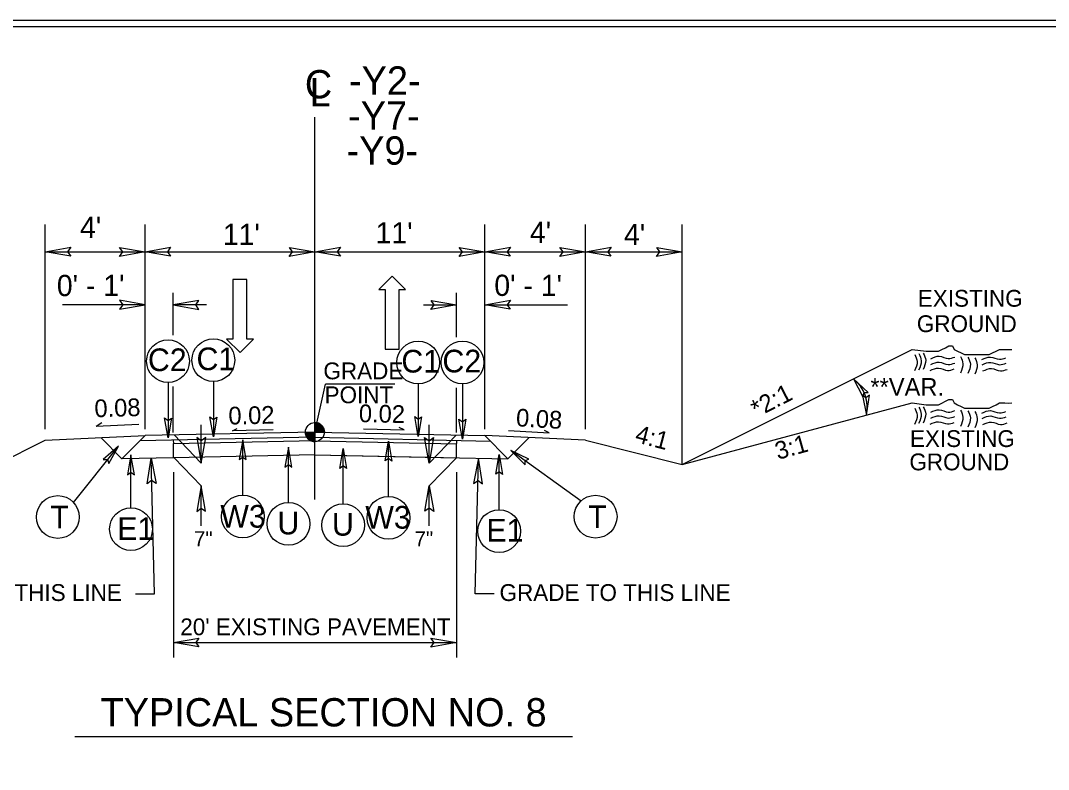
# Model space of a CAD drawing. Extents: x 573813 to 575363, y -54752 to -53123.
# Drawn here: x 574831.2 to 574913.7, y -53847.8 to -53787.7 of the extents above; entities that cross this region are included whole.
import ezdxf

# ---------------------------------------------------------------- set-up
doc = ezdxf.new("R2010")
doc.units = 0
for name, color, linetype in [('Old_Level_1', 7, 'Continuous'), ('Old_Level_11', 7, 'Continuous'), ('Old_Level_2', 7, 'Continuous'), ('Old_Level_3', 7, 'Continuous'), ('Prop Lane Arrow CELL', 7, 'Continuous'), ('Prop Pavement Schedule Description CELL', 7, 'Continuous'), ('Sheet Plot Border Inside CELL', 7, 'Continuous'), ('Sheet Typical CELL', 7, 'Continuous'), ('Typical Grade Point Symbol CELL', 7, 'Continuous'), ('Typical ID Circle CELL', 7, 'Continuous'), ('Typical Terminator CELL', 7, 'Continuous'), ('Typical Text ID Circle CELL', 7, 'Continuous')]:
    doc.layers.add(name, color=color, linetype=linetype)

msp = doc.modelspace()

# ---------------------------------------------------------------- linework, layer by layer
at = {"layer": 'Old_Level_1'}
for p, q in [((574884.321, -53823.332), (574902.797, -53814.094)), ((574884.321, -53823.332), (574902.797, -53818.396)), ((574854.816, -53820.732), (574841.173, -53821.015)), ((574848.192, -53820.63), (574848.571, -53820.44)), ((574851.461, -53820.562), (574848.192, -53820.63)), ((574854.816, -53820.732), (574868.46, -53821.015)), ((574858.709, -53820.477), (574861.972, -53820.545)), ((574861.972, -53820.545), (574861.593, -53820.356)), ((574799.389, -53838.269), (574833.158, -53821.384)), ((574833.158, -53821.384), (574841.173, -53821.015)), ((574837.62, -53821.179), (574839.315, -53822.874)), ((574841.173, -53821.015), (574839.315, -53822.874)), ((574854.816, -53821.14), (574840.755, -53821.433)), ((574843.444, -53821.377), (574843.447, -53821.662)), ((574854.816, -53821.435), (574843.447, -53821.663)), ((574843.447, -53822.788), (574843.447, -53821.662)), ((574854.816, -53821.14), (574868.915, -53821.471)), ((574854.816, -53821.435), (574866.186, -53821.663)), ((574866.189, -53821.407), (574866.186, -53821.661)), ((574866.186, -53822.788), (574866.186, -53821.661)), ((574868.46, -53821.015), (574870.318, -53822.874)), ((574876.54, -53821.387), (574868.46, -53821.015)), ((574872.013, -53821.179), (574870.318, -53822.874)), ((574876.54, -53821.387), (574884.321, -53823.332)), ((574854.816, -53822.552), (574843.447, -53822.788)), ((574854.816, -53822.551), (574866.186, -53822.788)), ((574854.816, -53822.551), (574870.318, -53822.874)), ((574843.447, -53822.788), (574839.315, -53822.874))]:
    msp.add_line(p, q, dxfattribs=at)
for points in [[(574902.797, -53814.094), (574903.917, -53814.234), (574904.198, -53814.234), (574904.618, -53814.234), (574904.898, -53814.234), (574905.179, -53814.094), (574905.459, -53813.954), (574905.739, -53813.813), (574906.019, -53813.813), (574906.16, -53814.094), (574906.44, -53814.234), (574906.72, -53814.374), (574907, -53814.514), (574907.28, -53814.514), (574907.561, -53814.514), (574907.841, -53814.514), (574908.121, -53814.514), (574908.401, -53814.514), (574908.681, -53814.514), (574908.961, -53814.514), (574909.242, -53814.374), (574909.522, -53814.234), (574909.802, -53814.094), (574910.223, -53814.094), (574910.503, -53814.094), (574910.783, -53814.094)], [(574902.797, -53818.396), (574903.917, -53818.536), (574904.198, -53818.536), (574904.618, -53818.536), (574904.898, -53818.536), (574905.179, -53818.397), (574905.459, -53818.256), (574905.739, -53818.115), (574906.019, -53818.115), (574906.16, -53818.396), (574906.44, -53818.536), (574906.72, -53818.677), (574907, -53818.816), (574907.28, -53818.816), (574907.561, -53818.816), (574907.841, -53818.816), (574908.121, -53818.816), (574908.401, -53818.816), (574908.681, -53818.816), (574908.961, -53818.816), (574909.242, -53818.677), (574909.522, -53818.536), (574909.802, -53818.396), (574910.223, -53818.396), (574910.503, -53818.397), (574910.783, -53818.396)]]:
    msp.add_lwpolyline(points, dxfattribs=at)
at = {"layer": 'Old_Level_11'}
for p, q in [((574833.158, -53820.494), (574833.158, -53804.056)), ((574841.173, -53820.494), (574841.173, -53804.056)), ((574868.46, -53820.494), (574868.46, -53804.056)), ((574876.54, -53820.494), (574876.54, -53804.056)), ((574884.321, -53823.295), (574884.321, -53804.056)), ((574833.158, -53806.256), (574841.173, -53806.256)), ((574841.173, -53806.256), (574854.816, -53806.256)), ((574854.816, -53806.256), (574868.46, -53806.256)), ((574868.46, -53806.256), (574876.54, -53806.256)), ((574876.54, -53806.256), (574884.321, -53806.256)), ((574843.444, -53812.959), (574843.444, -53809.559)), ((574866.189, -53813.118), (574866.189, -53809.559)), ((574841.173, -53810.514), (574834.531, -53810.514)), ((574846.104, -53810.514), (574843.444, -53810.514)), ((574863.529, -53810.514), (574866.189, -53810.514)), ((574868.46, -53810.514), (574875.102, -53810.514)), ((574843.444, -53820.768), (574843.444, -53817.071)), ((574854.816, -53820.732), (574855.66, -53816.884)), ((574861.226, -53816.884), (574855.66, -53816.884)), ((574866.189, -53820.768), (574866.189, -53817.188)), ((574845.691, -53823.22), (574845.691, -53820.144)), ((574863.994, -53823.221), (574863.994, -53820.145)), ((574843.506, -53820.957), (574845.691, -53823.22)), ((574866.169, -53820.968), (574863.994, -53823.221)), ((574841.933, -53833.725), (574841.666, -53822.825)), ((574843.499, -53822.787), (574845.684, -53825.049)), ((574866.186, -53822.788), (574864.001, -53825.051)), ((574867.7, -53833.725), (574867.967, -53822.825)), ((574843.447, -53823.959), (574843.447, -53838.833)), ((574866.186, -53823.959), (574866.186, -53838.833)), ((574845.684, -53828.261), (574845.684, -53825.049)), ((574864.001, -53828.262), (574864.001, -53825.051)), ((574840.42, -53833.725), (574841.933, -53833.725)), ((574869.213, -53833.725), (574867.7, -53833.725)), ((574843.447, -53837.641), (574866.186, -53837.641)), ((574835.537, -53845.192), (574875.496, -53845.192))]:
    msp.add_line(p, q, dxfattribs=at)
for points in [[(574835.204, -53806.608), (574833.158, -53806.256), (574835.216, -53805.892), (574834.954, -53806.256)], [(574839.126, -53805.904), (574841.173, -53806.256), (574839.115, -53806.62), (574839.376, -53806.256)], [(574843.219, -53806.608), (574841.173, -53806.256), (574843.231, -53805.892), (574842.969, -53806.256)], [(574852.77, -53805.904), (574854.816, -53806.256), (574852.759, -53806.62), (574853.02, -53806.256)], [(574856.863, -53806.608), (574854.816, -53806.256), (574856.874, -53805.892), (574856.613, -53806.256)], [(574866.414, -53805.904), (574868.46, -53806.256), (574866.402, -53806.62), (574866.664, -53806.256)], [(574870.507, -53806.608), (574868.46, -53806.256), (574870.518, -53805.892), (574870.257, -53806.256)], [(574874.494, -53805.904), (574876.54, -53806.256), (574874.482, -53806.62), (574874.744, -53806.256)], [(574878.587, -53806.609), (574876.54, -53806.256), (574878.598, -53805.892), (574878.337, -53806.256)], [(574882.275, -53805.904), (574884.321, -53806.256), (574882.263, -53806.62), (574882.524, -53806.256)], [(574839.126, -53810.866), (574841.173, -53810.514), (574839.115, -53810.15), (574839.376, -53810.514)], [(574845.491, -53810.161), (574843.444, -53810.514), (574845.502, -53810.877), (574845.241, -53810.514)], [(574864.142, -53810.161), (574866.189, -53810.514), (574864.131, -53810.877), (574864.392, -53810.514)], [(574870.507, -53810.866), (574868.46, -53810.514), (574870.518, -53810.15), (574870.257, -53810.514)], [(574845.339, -53821.173), (574845.691, -53823.22), (574846.055, -53821.162), (574845.691, -53821.423)], [(574864.346, -53821.174), (574863.994, -53823.221), (574863.63, -53821.163), (574863.994, -53821.424)], [(574841.357, -53824.878), (574841.666, -53822.825), (574842.074, -53824.874), (574841.704, -53824.621)], [(574868.276, -53824.878), (574867.967, -53822.825), (574867.559, -53824.874), (574867.928, -53824.621)], [(574846.036, -53827.096), (574845.684, -53825.049), (574845.32, -53827.107), (574845.683, -53826.846)], [(574863.649, -53827.097), (574864.001, -53825.051), (574864.365, -53827.109), (574864.002, -53826.847)], [(574845.493, -53837.993), (574843.447, -53837.641), (574845.505, -53837.277), (574845.243, -53837.641)], [(574864.14, -53837.288), (574866.186, -53837.641), (574864.128, -53838.005), (574864.39, -53837.641)]]:
    msp.add_lwpolyline(points, close=True, dxfattribs=at)
msp.add_arc((574896.259, -53818.758), 2.919, 347.68026, 51.87229, dxfattribs=at)
at = {"layer": 'Old_Level_2'}
for p, q in [((574854.816, -53826.151), (574854.816, -53795.432)), ((574837.257, -53820.252), (574837.711, -53819.959)), ((574837.257, -53820.252), (574840.687, -53820.085)), ((574870.378, -53820.593), (574873.628, -53820.787)), ((574873.628, -53820.787), (574873.245, -53820.605))]:
    msp.add_line(p, q, dxfattribs=at)
for points in [[(574902.992, -53814.497), (574903.184, -53815.061), (574902.977, -53815.81)], [(574902.992, -53814.497), (574903.184, -53815.061), (574902.977, -53815.81)], [(574903.324, -53814.432), (574903.514, -53814.998), (574903.307, -53815.748)], [(574903.324, -53814.432), (574903.514, -53814.998), (574903.307, -53815.748)], [(574903.678, -53814.395), (574903.872, -53814.961), (574903.664, -53815.708)], [(574903.678, -53814.395), (574903.872, -53814.961), (574903.664, -53815.708)], [(574904.278, -53815.311), (574904.964, -53815.118), (574905.684, -53815.302), (574906.204, -53815.185)], [(574904.278, -53815.311), (574904.964, -53815.118), (574905.684, -53815.302), (574906.204, -53815.185)], [(574904.282, -53814.836), (574904.964, -53814.639), (574905.69, -53814.823), (574906.209, -53814.706)], [(574906.674, -53814.674), (574906.864, -53815.238), (574906.66, -53815.987)], [(574906.674, -53814.674), (574906.864, -53815.238), (574906.66, -53815.987)], [(574907.27, -53814.72), (574907.462, -53815.286), (574907.257, -53816.035)], [(574907.27, -53814.72), (574907.462, -53815.286), (574907.257, -53816.035)], [(574907.822, -53814.77), (574908.014, -53815.336), (574907.806, -53816.083)], [(574907.822, -53814.77), (574908.014, -53815.336), (574907.806, -53816.083)], [(574908.387, -53814.9), (574909.073, -53814.705), (574909.793, -53814.889), (574910.316, -53814.774)], [(574908.406, -53815.329), (574909.091, -53815.132), (574909.811, -53815.319), (574910.334, -53815.201)], [(574908.406, -53815.329), (574909.091, -53815.132), (574909.811, -53815.319), (574910.334, -53815.201)], [(574904.225, -53815.792), (574904.909, -53815.599), (574905.635, -53815.779), (574906.156, -53815.664)], [(574904.225, -53815.792), (574904.909, -53815.599), (574905.635, -53815.779), (574906.156, -53815.664)], [(574908.475, -53815.826), (574909.159, -53815.63), (574909.883, -53815.815), (574910.403, -53815.697)], [(574908.475, -53815.826), (574909.159, -53815.63), (574909.883, -53815.815), (574910.403, -53815.697)], [(574902.992, -53818.799), (574903.184, -53819.363), (574902.977, -53820.112)], [(574902.992, -53818.799), (574903.184, -53819.363), (574902.977, -53820.112)], [(574903.324, -53818.734), (574903.514, -53819.3), (574903.307, -53820.05)], [(574903.324, -53818.734), (574903.514, -53819.3), (574903.307, -53820.05)], [(574903.678, -53818.697), (574903.872, -53819.263), (574903.664, -53820.01)], [(574903.678, -53818.697), (574903.872, -53819.263), (574903.664, -53820.01)], [(574904.282, -53819.138), (574904.964, -53818.941), (574905.69, -53819.125), (574906.209, -53819.008)], [(574906.674, -53818.976), (574906.864, -53819.54), (574906.66, -53820.29)], [(574906.674, -53818.976), (574906.864, -53819.54), (574906.66, -53820.29)], [(574907.27, -53819.022), (574907.462, -53819.588), (574907.257, -53820.338)], [(574907.27, -53819.022), (574907.462, -53819.588), (574907.257, -53820.338)], [(574907.822, -53819.072), (574908.014, -53819.638), (574907.806, -53820.385)], [(574907.822, -53819.072), (574908.014, -53819.638), (574907.806, -53820.385)], [(574908.387, -53819.202), (574909.073, -53819.007), (574909.793, -53819.192), (574910.316, -53819.076)], [(574904.225, -53820.094), (574904.909, -53819.901), (574905.635, -53820.081), (574906.156, -53819.966)], [(574904.225, -53820.094), (574904.909, -53819.901), (574905.635, -53820.081), (574906.156, -53819.966)], [(574904.278, -53819.613), (574904.964, -53819.42), (574905.684, -53819.605), (574906.204, -53819.487)], [(574904.278, -53819.613), (574904.964, -53819.42), (574905.684, -53819.605), (574906.204, -53819.487)], [(574908.406, -53819.632), (574909.091, -53819.434), (574909.811, -53819.621), (574910.334, -53819.504)], [(574908.406, -53819.632), (574909.091, -53819.434), (574909.811, -53819.621), (574910.334, -53819.504)], [(574908.475, -53820.128), (574909.159, -53819.933), (574909.883, -53820.117), (574910.403, -53819.999)], [(574908.475, -53820.128), (574909.159, -53819.933), (574909.883, -53820.117), (574910.403, -53819.999)]]:
    msp.add_spline(points, degree=3, dxfattribs=at)
at = {"layer": 'Prop Lane Arrow CELL'}
for p, q in [((574848.234, -53808.484), (574848.234, -53813.259)), ((574849.36, -53808.484), (574848.234, -53808.484)), ((574849.36, -53813.259), (574849.36, -53808.484)), ((574861.031, -53808.213), (574859.94, -53809.288)), ((574862.089, -53809.288), (574861.031, -53808.213)), ((574859.94, -53809.288), (574860.452, -53809.288)), ((574860.452, -53809.288), (574860.452, -53814.063)), ((574861.577, -53814.063), (574861.577, -53809.288)), ((574861.577, -53809.288), (574862.089, -53809.288)), ((574848.234, -53813.259), (574847.723, -53813.259)), ((574847.723, -53813.259), (574848.814, -53814.334)), ((574848.814, -53814.334), (574849.872, -53813.259)), ((574849.872, -53813.259), (574849.36, -53813.259)), ((574860.452, -53814.063), (574861.577, -53814.063))]:
    msp.add_line(p, q, dxfattribs=at)
at = {"layer": 'Sheet Plot Border Inside CELL'}
msp.add_lwpolyline([(575005.811, -53787.681), (574672.332, -53787.681), (574672.332, -53998.814), (575005.811, -53998.814)], close=True, dxfattribs=at)
at = {"layer": 'Sheet Typical CELL'}
msp.add_lwpolyline([(575003.31, -53788.191), (574703.149, -53788.191), (574703.149, -53998.304), (575003.31, -53998.304)], close=True, dxfattribs=at)
at = {"layer": 'Typical Grade Point Symbol CELL'}
for p, q in [((574854.816, -53820.732), (574854.816, -53819.968)), ((574854.053, -53820.732), (574854.816, -53820.732)), ((574854.815, -53821.495), (574854.816, -53820.732)), ((574854.816, -53820.732), (574854.815, -53821.495)), ((574855.58, -53820.732), (574854.816, -53820.732))]:
    msp.add_line(p, q, dxfattribs=at)
for points in [[(574854.823, -53819.968), (574854.823, -53819.968), (574854.823, -53820.732)], [(574854.839, -53819.968), (574854.839, -53820.732)], [(574854.854, -53819.97), (574854.854, -53820.732)], [(574854.869, -53819.97), (574854.869, -53820.732)], [(574854.884, -53819.972), (574854.884, -53820.732)], [(574854.9, -53819.973), (574854.9, -53820.732)], [(574854.915, -53819.975), (574854.915, -53820.732)], [(574854.93, -53819.977), (574854.93, -53820.732)], [(574854.945, -53819.978), (574854.945, -53820.732)], [(574854.961, -53819.982), (574854.961, -53820.732)], [(574854.976, -53819.985), (574854.976, -53820.732)], [(574854.991, -53819.989), (574854.991, -53820.732)], [(574855.007, -53819.992), (574855.007, -53820.732)], [(574855.022, -53819.997), (574855.022, -53820.732)], [(574855.037, -53820.001), (574855.037, -53820.732)], [(574855.052, -53820.006), (574855.052, -53820.732)], [(574855.068, -53820.011), (574855.068, -53820.732)], [(574855.083, -53820.016), (574855.083, -53820.732)], [(574855.098, -53820.023), (574855.098, -53820.732)], [(574855.113, -53820.029), (574855.113, -53820.732)], [(574855.129, -53820.036), (574855.129, -53820.732)], [(574855.144, -53820.043), (574855.144, -53820.732)], [(574855.159, -53820.05), (574855.159, -53820.732)], [(574855.174, -53820.058), (574855.174, -53820.732)], [(574855.19, -53820.067), (574855.19, -53820.732)], [(574855.205, -53820.075), (574855.205, -53820.732)], [(574855.22, -53820.084), (574855.22, -53820.732)], [(574855.235, -53820.094), (574855.235, -53820.732)], [(574855.251, -53820.104), (574855.251, -53820.732)], [(574855.266, -53820.116), (574855.266, -53820.732)], [(574855.281, -53820.126), (574855.281, -53820.732)], [(574855.297, -53820.138), (574855.297, -53820.732)], [(574855.312, -53820.151), (574855.312, -53820.732)], [(574855.327, -53820.165), (574855.327, -53820.732)], [(574854.057, -53820.732), (574854.057, -53820.815)], [(574854.072, -53820.732), (574854.072, -53820.905)], [(574854.087, -53820.732), (574854.087, -53820.959)], [(574854.102, -53820.732), (574854.102, -53821.005)], [(574854.118, -53820.732), (574854.118, -53821.04)], [(574854.133, -53820.732), (574854.133, -53821.073)], [(574854.148, -53820.732), (574854.148, -53821.101)], [(574854.163, -53820.732), (574854.163, -53821.129)], [(574854.179, -53820.732), (574854.179, -53821.152)], [(574854.194, -53820.732), (574854.194, -53821.174)], [(574854.209, -53820.732), (574854.209, -53821.195)], [(574854.224, -53820.732), (574854.224, -53821.213)], [(574854.24, -53820.732), (574854.24, -53821.232)], [(574854.255, -53820.732), (574854.255, -53821.249)], [(574854.27, -53820.732), (574854.27, -53821.266)], [(574854.286, -53820.732), (574854.286, -53821.281)], [(574854.301, -53820.732), (574854.301, -53821.295)], [(574854.316, -53820.732), (574854.316, -53821.308)], [(574854.331, -53820.732), (574854.331, -53821.322)], [(574854.347, -53820.732), (574854.347, -53821.334)], [(574854.362, -53820.732), (574854.362, -53821.346)], [(574854.377, -53820.732), (574854.377, -53821.356)], [(574854.392, -53820.732), (574854.392, -53821.366)], [(574854.408, -53820.732), (574854.408, -53821.376)], [(574854.423, -53820.732), (574854.423, -53821.386)], [(574854.438, -53820.732), (574854.438, -53821.395)], [(574854.453, -53820.732), (574854.453, -53821.403)], [(574854.469, -53820.732), (574854.469, -53821.412)], [(574854.484, -53820.732), (574854.484, -53821.419)], [(574854.499, -53820.732), (574854.499, -53821.425)], [(574854.515, -53820.732), (574854.515, -53821.432)], [(574854.53, -53820.732), (574854.53, -53821.439)], [(574854.545, -53820.732), (574854.545, -53821.446)], [(574854.56, -53820.732), (574854.56, -53821.451)], [(574854.576, -53820.732), (574854.576, -53821.456)], [(574854.591, -53820.732), (574854.591, -53821.461)], [(574854.606, -53820.732), (574854.606, -53821.464)], [(574854.621, -53820.732), (574854.621, -53821.47)], [(574854.637, -53820.732), (574854.637, -53821.473)], [(574854.652, -53820.732), (574854.652, -53821.476)], [(574854.667, -53820.732), (574854.667, -53821.48)], [(574854.682, -53820.732), (574854.682, -53821.483)], [(574854.698, -53820.732), (574854.698, -53821.485)], [(574854.713, -53820.732), (574854.713, -53821.488)], [(574854.728, -53820.732), (574854.728, -53821.49)], [(574854.744, -53820.732), (574854.744, -53821.492)], [(574854.759, -53820.732), (574854.759, -53821.493)], [(574854.774, -53820.732), (574854.774, -53821.493)], [(574854.789, -53820.732), (574854.789, -53821.495)], [(574854.805, -53820.732), (574854.805, -53821.495), (574854.805, -53821.495)], [(574855.342, -53820.179), (574855.342, -53820.732)], [(574855.358, -53820.194), (574855.358, -53820.732)], [(574855.373, -53820.209), (574855.373, -53820.732)], [(574855.388, -53820.226), (574855.388, -53820.732)], [(574855.403, -53820.245), (574855.403, -53820.732)], [(574855.419, -53820.263), (574855.419, -53820.732)], [(574855.434, -53820.284), (574855.434, -53820.732)], [(574855.449, -53820.306), (574855.449, -53820.732)], [(574855.465, -53820.33), (574855.465, -53820.732)], [(574855.48, -53820.355), (574855.48, -53820.732)], [(574855.495, -53820.382), (574855.495, -53820.732)], [(574855.51, -53820.414), (574855.51, -53820.732)], [(574855.526, -53820.45), (574855.526, -53820.732)], [(574855.541, -53820.492), (574855.541, -53820.732)], [(574855.556, -53820.545), (574855.556, -53820.732)], [(574855.571, -53820.623), (574855.571, -53820.732)]]:
    msp.add_lwpolyline(points, dxfattribs=at)
msp.add_circle((574854.816, -53820.731), 0.763, dxfattribs=at)
for start, end in [(359.99048, 89.99048), (179.99048, 269.99048)]:
    msp.add_arc((574854.816, -53820.731), 0.763, start, end, dxfattribs=at)
at = {"layer": 'Typical ID Circle CELL'}
for p, q in [((574843.017, -53816.754), (574843.017, -53821.193)), ((574846.659, -53816.68), (574846.659, -53821.119)), ((574866.671, -53816.859), (574866.671, -53821.298)), ((574863.113, -53816.869), (574863.113, -53821.091)), ((574849.028, -53825.787), (574849.028, -53821.348)), ((574860.721, -53825.897), (574860.721, -53821.458)), ((574835.424, -53826.384), (574839.037, -53821.853)), ((574840.045, -53826.811), (574840.045, -53822.566)), ((574852.691, -53826.389), (574852.691, -53821.951)), ((574857.079, -53826.492), (574857.079, -53822.054)), ((574869.611, -53826.966), (574869.611, -53822.528)), ((574876.211, -53826.277), (574870.558, -53822.21))]:
    msp.add_line(p, q, dxfattribs=at)
for centre in [(574843.017, -53815.037), (574846.659, -53814.963), (574863.113, -53815.152), (574866.671, -53815.142), (574834.165, -53827.553), (574849.028, -53827.504), (574860.721, -53827.614), (574877.362, -53827.524), (574852.691, -53828.106), (574857.079, -53828.209), (574840.045, -53828.529), (574869.611, -53828.684)]:
    msp.add_circle(centre, 1.718, dxfattribs=at)
at = {"layer": 'Typical Terminator CELL'}
for points in [[(574899.253, -53817.55), (574898.061, -53816.462), (574898.819, -53817.898), (574898.918, -53817.564)], [(574898.792, -53817.799), (574899.11, -53819.381), (574899.348, -53817.775), (574899.071, -53817.986)], [(574843.291, -53819.602), (574843.017, -53821.193), (574842.734, -53819.594), (574843.017, -53819.797)], [(574846.933, -53819.529), (574846.659, -53821.119), (574846.377, -53819.52), (574846.659, -53819.723)], [(574863.386, -53819.501), (574863.113, -53821.091), (574862.83, -53819.492), (574863.113, -53819.696)], [(574866.945, -53819.707), (574866.671, -53821.298), (574866.388, -53819.698), (574866.671, -53819.902)], [(574849.302, -53822.938), (574849.028, -53821.348), (574848.745, -53822.947), (574849.028, -53822.744)], [(574860.447, -53823.048), (574860.721, -53821.458), (574861.004, -53823.057), (574860.721, -53822.854)], [(574838.26, -53823.268), (574839.037, -53821.853), (574837.819, -53822.927), (574838.167, -53822.945)], [(574840.319, -53824.157), (574840.045, -53822.566), (574839.762, -53824.165), (574840.045, -53823.962)], [(574852.965, -53823.541), (574852.691, -53821.951), (574852.408, -53823.55), (574852.691, -53823.347)], [(574856.805, -53823.644), (574857.079, -53822.054), (574857.362, -53823.653), (574857.079, -53823.45)], [(574869.338, -53824.118), (574869.612, -53822.528), (574869.894, -53824.127), (574869.612, -53823.924)], [(574872.009, -53822.916), (574870.558, -53822.21), (574871.691, -53823.373), (574871.691, -53823.025)]]:
    msp.add_lwpolyline(points, close=True, dxfattribs=at)

# ---------------------------------------------------------------- texts
at = {"layer": 'Old_Level_1'}
for s, height, rotation, p in [('EXISTING', 1.3502, 359.99996, (574903.237, -53810.664)), ('GROUND', 1.3502, 359.99996, (574903.161, -53812.704)), ('*2:1', 1.4213, 27.08551, (574890.293, -53819.601)), ('0.08', 1.4212, 1.66332, (574837.128, -53819.545)), ('0.02', 1.4212, 358.80838, (574858.337, -53819.93)), ('0.02', 1.4212, 1.19188, (574847.884, -53820.129)), ('0.08', 1.4212, 356.57937, (574870.939, -53820.26)), ('4:1', 1.4212, 345.34321, (574880.454, -53821.514)), ('EXISTING', 1.3498, 359.99996, (574902.608, -53821.931)), ('3:1', 1.4208, 15.63504, (574891.998, -53822.97)), ('GROUND', 1.3498, 359.99996, (574902.563, -53823.803)), ('TYPICAL SECTION NO. 8', 2.27395, 359.99996, (574837.603, -53844.374))]:
    msp.add_text(s, height=height, rotation=rotation, dxfattribs=at).set_placement(p)
msp.add_text('**VAR.', height=1.4208, dxfattribs=at).set_placement((574899.431, -53817.814))
at = {"layer": 'Old_Level_11'}
for s, height, rotation, p in [("11'", 1.7055, 359.99996, (574847.423, -53805.704)), ("11'", 1.7055, 359.99996, (574859.691, -53805.582)), ("4'", 1.7055, 359.99996, (574879.642, -53805.716)), ('GRADE TO THIS LINE', 1.35016, 0.00004, (574820.754, -53834.297)), ('GRADE TO THIS LINE', 1.35016, 359.99996, (574869.645, -53834.297)), ("20' EXISTING PAVEMENT", 1.35016, 359.99996, (574844.005, -53837.047))]:
    msp.add_text(s, height=height, rotation=rotation, dxfattribs=at).set_placement(p)
at = {"layer": 'Old_Level_2'}
for s, rotation, p in [('C', 359.99996, (574854.009, -53793.931)), ('L', 359.94686, (574854.396, -53794.568))]:
    msp.add_text(s, height=2.274, rotation=rotation, dxfattribs=at).set_placement(p)
at = {"layer": 'Old_Level_3'}
for s, height, rotation, p in [('-Y2-', 2.2739, 0, (574857.557, -53793.632)), ('-Y7-', 2.2739, 0, (574857.486, -53796.447)), ('-Y9-', 2.2739, 0, (574857.359, -53799.254)), ("4'", 1.7055, 359.83288, (574835.947, -53805.136)), ("4'", 1.7055, 359.83288, (574872.08, -53805.541)), ("0' - 1'", 1.7055, 0.16712, (574834.093, -53809.814)), ("0' - 1'", 1.7055, 359.83288, (574869.223, -53809.795)), ('GRADE', 1.3502, 359.99996, (574855.499, -53816.492)), ('POINT', 1.3502, 359.99996, (574855.592, -53818.415))]:
    msp.add_text(s, height=height, rotation=rotation, dxfattribs=at).set_placement(p)
at = {"layer": 'Prop Pavement Schedule Description CELL'}
for s, height, p in [('C2', 1.8192, (574841.405, -53815.834)), ('C1', 1.8192, (574845.308, -53815.76)), ('C1', 1.8192, (574861.761, -53815.95)), ('C2', 1.8192, (574865.059, -53815.939)), ('T', 1.819, (574833.567, -53828.463)), ('W3', 1.8192, (574847.22, -53828.408)), ('W3', 1.8192, (574858.864, -53828.487)), ('T', 1.819, (574876.764, -53828.434)), ('E1', 1.8192, (574838.94, -53829.392)), ('U', 1.819, (574851.802, -53828.95)), ('U', 1.819, (574856.189, -53829.053)), ('E1', 1.8192, (574868.587, -53829.527))]:
    msp.add_text(s, height=height, rotation=360, dxfattribs=at).set_placement(p)
at = {"layer": 'Typical Text ID Circle CELL'}
for p in [(574845.101, -53829.92), (574862.817, -53829.921)]:
    msp.add_text('7"', height=1.2298, dxfattribs=at).set_placement(p)

doc.saveas('drawing.dxf')
